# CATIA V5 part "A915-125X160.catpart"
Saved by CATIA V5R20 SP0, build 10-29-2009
Part number: A915-125X160
Source: Unknown
Property "A": "75.000"
Property "ARTICLENO": "A915-125X160"
Property "BOMINFO": "A915-125X160"
Property "CODE": "A915-125X160"
Property "CREATOR": "CADENAS GmbH"
Property "D": "13.500"
Property "D1": "20.000"
Property "FORM": "C"
Property "L": "160.000"
Property "L1": "25.000"
Property "L2": "110.000"
Property "LINA": "A915-125X160"
Property "NB": "A915-125X160"
Property "NBSYN": "$CODE."
Property "NN": "A915"
Property "NT": "VDI 3357 Wear Plates, steel"
Property "SCREW": "M12x25"
Property "SUPPLIER": "CF"
Property "T": "13.000"
Property "W": "125.000"
Bounding box of the stored display mesh (mm): x 0 to 20, y 0 to 160, z -62.5 to 62.5
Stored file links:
  C:\Users\borellobunino\Desktop\3D X SITO CF\A915\GSB_OILLESS_G22501125160\CATIAV5\A915-125X160.catpart
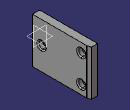
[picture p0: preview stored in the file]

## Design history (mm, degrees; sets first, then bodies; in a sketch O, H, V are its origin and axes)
Body1 "Geometry.1" (main body)
  Solid1 "A915-125X160.catpart": solid without history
